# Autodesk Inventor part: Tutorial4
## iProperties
Shininess: 64.0
Length Units: 11269
Angle Units: 11279
Time Units: 11290
Mass Units: 11283
Length Display Precision: 3
Angle Display Precision: 2
Compacted: True
Part Number: Tutorial4
Document SubType Name: Modeling
Created: 2002-12
Designer: deepak
Density: 1 g/cm^3
Density: 0.0
Volumn: 0.0
Area: 0.0
PropertySet Name: Model Information
Control State: 0
Master: False
Checked Out: False
Author: deepak
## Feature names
1. Revolution1
2. Chamfer2
